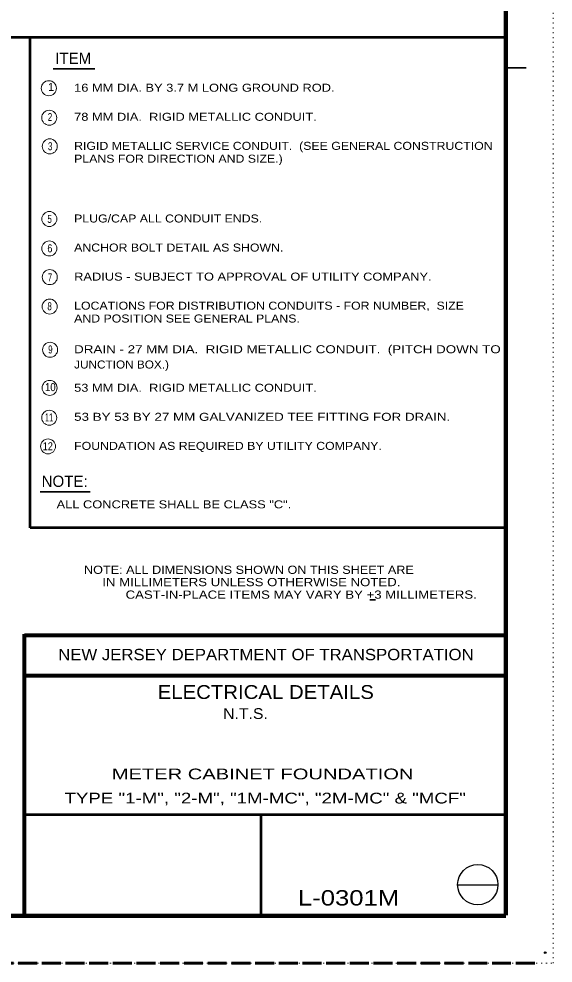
# Model space of a CAD drawing. Extents: x 312583 to 312854, y 144419 to 144597.
# Drawn here: x 312802.8 to 312853.5, y 144418.6 to 144508.3 of the extents above; entities that cross this region are included whole.
import ezdxf
from ezdxf.enums import TextEntityAlignment as Align

# ---------------------------------------------------------------- set-up
doc = ezdxf.new("R2010")
doc.units = 0
doc.header["$LTSCALE"] = 0.3
doc.header["$PDMODE"] = 32
doc.header["$PDSIZE"] = 0.15
doc.linetypes.add('DOTTED', pattern=[1.5, 0.3, -1.2])
doc.linetypes.add('LONG_DASHED', pattern=[7.5, 6, -1.5])
for name, color, linetype, lineweight in [('1', 7, 'Continuous', 25), ('10', 7, 'Continuous', 25), ('2', 7, 'Continuous', 13), ('63', 7, 'DOTTED', 13)]:
    doc.layers.add(name, color=color, linetype=linetype, lineweight=lineweight)

msp = doc.modelspace()

# ---------------------------------------------------------------- linework, layer by layer
at = {"layer": '1', "lineweight": 158}
for p, q in [((312849, 144423.1446), (312849, 144585.0846)), ((312616.5, 144423.0846), (312849, 144423.0846))]:
    msp.add_line(p, q, dxfattribs=at)
at = {"layer": '1', "lineweight": 53}
for p, q in [((312849, 144506.4889), (312616.5, 144506.4889)), ((312803.8301, 144459.9268), (312803.8301, 144506.4889)), ((312849, 144459.9268), (312803.8301, 144459.9268)), ((312849, 144432.6666), (312803.161, 144432.6666)), ((312825.7547, 144432.6666), (312825.7547, 144423.1446))]:
    msp.add_line(p, q, dxfattribs=at)
at = {"layer": '1', "lineweight": 35}
for p, q in [((312849, 144503.6216), (312850.932, 144503.6216)), ((312836.111, 144453.0808), (312836.6209, 144453.0808))]:
    msp.add_line(p, q, dxfattribs=at)
at = {"layer": '1', "lineweight": 80}
for p, q in [((312803.31, 144423.1446), (312803.31, 144449.8146)), ((312803.31, 144449.7246), (312849, 144449.7246)), ((312803.31, 144445.9146), (312849, 144445.9146))]:
    msp.add_line(p, q, dxfattribs=at)
at = {"layer": '1', "linetype": 'LONG_DASHED', "lineweight": 60}
msp.add_line((312851.75, 144418.5846), (312583.526, 144418.5846), dxfattribs=at)
at = {"layer": '1'}
msp.add_point((312852.75, 144419.5846), dxfattribs=at)
at = {"layer": '10'}
msp.add_line((312844.4384, 144426.0259), (312848.2794, 144426.0259), dxfattribs=at)
msp.add_circle((312846.3494, 144426.0405), 1.9159, dxfattribs=at)
at = {"layer": '2', "lineweight": 35}
for p, q in [((312806.0245, 144503.5377), (312809.9846, 144503.5377)), ((312804.801, 144463.3338), (312809.5514, 144463.3338))]:
    msp.add_line(p, q, dxfattribs=at)
at = {"layer": '2'}
for centre in [(312805.6159, 144501.6823), (312805.6542, 144498.884), (312805.7002, 144496.1623), (312805.6619, 144489.2623), (312805.6619, 144486.464), (312805.7002, 144483.7423), (312805.6926, 144480.944), (312805.7309, 144476.8423), (312805.6877, 144473.2227), (312805.6542, 144470.387), (312805.5392, 144467.6653)]:
    msp.add_circle(centre, 0.7147, dxfattribs=at)
at = {"layer": '63'}
msp.add_lwpolyline([(312601.2, 144418.5846), (312853.5, 144418.5846), (312853.5, 144596.7846)], dxfattribs=at)

# ---------------------------------------------------------------- texts
at = {"layer": '1'}
for s, width, p in [('NOTE: ALL DIMENSIONS SHOWN ON THIS SHEET ARE', 1.15, (312808.9531, 144455.556)), ('     IN MILLIMETERS UNLESS OTHERWISE NOTED.', 1.2, (312808.953, 144454.386)), ('CAST-IN-PLACE ITEMS MAY VARY BY +3 MILLIMETERS.', 1.2, (312812.9039, 144453.1951))]:
    msp.add_text(s, height=0.78, dxfattribs=dict(at, width=width)).set_placement(p)
for s, height, width, p in [('NEW JERSEY DEPARTMENT OF TRANSPORTATION', 1.08, 1.1, (312826.2285, 144447.3546)), ('ELECTRICAL DETAILS', 1.315, 1.1, (312826.2109, 144443.6759)), ('L-0301M   ', 1.457, 1.25, (312835.0904, 144424.0569))]:
    msp.add_text(s, height=height, dxfattribs=dict(at, width=width)).set_placement(p, align=Align.CENTER)
at = {"layer": '2'}
for s, p in [('ITEM', (312807.9281, 144503.9977)), ('NOTE:', (312807.1136, 144463.8183))]:
    msp.add_text(s, height=1.07, dxfattribs=at).set_placement(p, align=Align.CENTER)
msp.add_text('1 ', height=0.76, dxfattribs=at).set_placement((312805.5452, 144501.4265))
for s, width, p in [('16 MM DIA. BY 3.7 M LONG GROUND ROD.', 1.2, (312808.0156, 144501.3517)), ('2', 0.75, (312805.5128, 144498.573)), ('78 MM DIA.  RIGID METALLIC CONDUIT.', 1.2, (312808.0156, 144498.5917)), ('3', 0.75, (312805.5315, 144495.7944)), ('RIGID METALLIC SERVICE CONDUIT.  (SEE GENERAL CONSTRUCTION', 1.15, (312808.0156, 144495.8317)), ('PLANS FOR DIRECTION AND SIZE.)', 1.15, (312808.0156, 144494.6117)), ('5', 0.75, (312805.4754, 144488.8943)), ('PLUG/CAP ALL CONDUIT ENDS.', 1.15, (312808.0156, 144488.9317)), ('6', 0.85, (312805.4724, 144486.0969)), ('ANCHOR BOLT DETAIL AS SHOWN.', 1.15, (312808.0156, 144486.1717)), ('7', 0.75, (312805.5127, 144483.3369)), ('RADIUS - SUBJECT TO APPROVAL OF UTILITY COMPANY.', 1.2, (312808.0156, 144483.4117)), ('8', 0.75, (312805.4754, 144480.5956)), ('LOCATIONS FOR DISTRIBUTION CONDUITS - FOR NUMBER,  SIZE', 1.15, (312808.0156, 144480.6517)), ('AND POSITION SEE GENERAL PLANS.', 1.15, (312808.0156, 144479.4317)), ('9', 0.75, (312805.5497, 144476.493)), ('DRAIN - 27 MM DIA.  RIGID METALLIC CONDUIT.  (PITCH DOWN TO ', 1.25, (312808.0156, 144476.5117)), ('JUNCTION BOX.)', 1.1, (312808.0156, 144475.0627)), ('10', 0.9, (312805.2445, 144472.9108)), ('53 MM DIA.  RIGID METALLIC CONDUIT.', 1.2, (312808.0156, 144472.8547)), ('11', 0.7, (312805.2437, 144470.0387)), ('53 BY 53 BY 27 MM GALVANIZED TEE FITTING FOR DRAIN.', 1.25, (312808.0156, 144470.0947)), ('12', 0.85, (312805.0362, 144467.2973)), ('FOUNDATION AS REQUIRED BY UTILITY COMPANY.', 1.15, (312808.0156, 144467.3347)), ('ALL CONCRETE SHALL BE CLASS "C".', 1.2, (312806.3491, 144461.7795))]:
    msp.add_text(s, height=0.76, dxfattribs=dict(at, width=width)).set_placement(p)
for s, width, p in [('    N.T.S.  ', 1.1, (312823.87, 144441.778)), ('          METER CABINET FOUNDATION          ', 1.4, (312825.9157, 144436.0399)), ('TYPE "1-M", "2-M", "1M-MC", "2M-MC" & "MCF"', 1.3, (312826.1602, 144433.7476))]:
    msp.add_text(s, height=1.02, dxfattribs=dict(at, width=width)).set_placement(p, align=Align.CENTER)

doc.saveas('drawing.dxf')
